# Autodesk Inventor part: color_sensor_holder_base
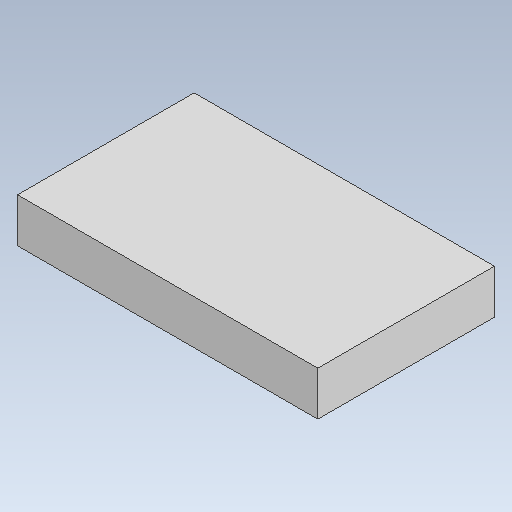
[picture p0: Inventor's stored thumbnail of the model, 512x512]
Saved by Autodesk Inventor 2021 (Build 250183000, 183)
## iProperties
Created: 2026-10
Part Number: color_sensor_holder_base
Material: Generic
Document SubType Name: Modeling
Designer: alolo
Density: 1 g/cm^3
Appearance: Default
Author: alolo
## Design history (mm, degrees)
sketch "Sketch1"
  geometry: L1 (0, 0)-(34, 0); L2 (34, 0)-(34, -20); L3 (34, -20)-(0, -20); L4 (0, -20)-(0, 0)
  constraints: 8 end point, 2 parallel, 1 horizontal, 1 perpendicular
  dimensions: "d0" = 34 distance of L2.end L3.end; "d1" = 20 distance of L1.end L2.end
extrude "Extrusion1" new body sketch "Sketch1" distance "d2" = 5 (= wood_thickness); taper "d3" = 0 deg
body "Solid1"
other parameters: "slide_length" = 195 [user parameter], "slide_angle" = 7 deg [user parameter], "slide_width" = 65 [user parameter], "wood_thickness" = 5 [user parameter; used in 1 equation term], "aclyric_thickness" = 6 [user parameter]
